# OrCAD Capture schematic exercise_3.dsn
size A
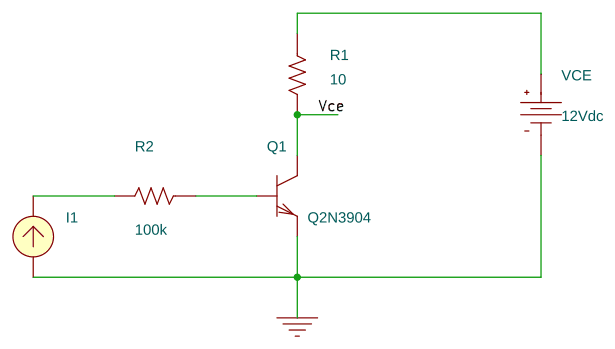
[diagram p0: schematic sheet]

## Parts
I1  IDC
Q1  Q2N3904  [to92]
R1  10  [AXRC05]
R2  100k  [AXRC05]
VCE  VDC

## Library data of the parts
I1 = IDC
Q1 = Q2N3904
R1 R2 = R
VCE = VDC: DC: 12Vdc

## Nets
0: I1.1(+) Q1.1(e) VCE.1(-)
Vce: Q1.3(c) R1.2
N00508: Q1.2(b) R2.1
N00581: I1.2(-) R2.2
N00612: R1.1 VCE.0(+)
